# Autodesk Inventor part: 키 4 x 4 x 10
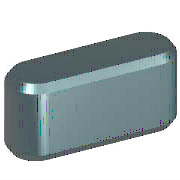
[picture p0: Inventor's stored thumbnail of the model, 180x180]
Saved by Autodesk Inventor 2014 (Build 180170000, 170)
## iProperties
IsCustomPart: 1
Created: 2012-02
Part Number: 키 4 x 4 x 10
Material: 강철, 연강
Description: 키 및 해당 키홈
Document SubType Name: Modeling
Standard: KS B 1311
Designer: test
Standards Organization: KS
Language: ko-KR
Size Designation: 4 x 4 x 10
Categories: <MemberInstance><Categories><Category DisplayName="샤프트 부품" InternalName="7f7aeb1f-a693-4053-b835-cee3144e0d98" Mnemonic="SHFT"><Category DisplayName="키" Interna
Density: 7.86 g/cm^3
Appearance: 강철
Mass: 1.13784 g
Surface Area: 1.6404 cm^2
Volume: 0.144763 cm^3
Author: test
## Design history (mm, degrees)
workplane "Work Plane1"
workplane "Work Plane2"
sketch "스케치1"
  geometry: L1 (2, 2)-(8, 2); L2 (8, -2)-(2, -2); L3 (0, 9.4)-(0, -7.4) reference; L4 (-5, 0)-(30, 0) reference; L5 (10, 0)-(10, 7); A1 r 2 centre (2, 0) between (2, 2) and (2, -2); A2 r 2 centre (8, 0) between (8, -2) and (8, 2)
  constraints: 6 end point, 5 point on circle, 4 tangent, 3 point on line, 2 centre point, 1 horizontal, 1 parallel, 1 perpendicular
  dimensions: "d0" = 2 radius of A1 (= 0.5 x PB); "d13" = 2 radius of A2 (= 0.5 x PB); "d14" = 10 distance between parallel lines of L5 L3 (= NLG)
extrude "본체1" new body sketch "스케치1" taper "d3" = 0 deg; stored distance "d4" = 10
workplane "Work Plane3"
body "Solid1"
chamfer "모따기1" distance "d8" = 0.25 (= PHH); stored, may be unused: second distance "d9" = 0.25 (= PHH), angle "d15" = 45 deg
other parameters: "d1" = -2.5 (= -PNT), "d2" = 1.5 (= PH - PNT), "NLG" = 10 [user parameter; used in 3 equation terms], "PB" = 4 [user parameter; used in 2 equation terms], "PNT" = 2.5 [user parameter; used in 2 equation terms], "PH" = 4 [user parameter; used in 1 equation term], "PHH" = 0.25 [user parameter; used in 2 equation terms], "d10" = 0, "d16" = 0, "d17" = 0, "d18" = 0, "WDMAX" = 12 [user parameter], "RR" = 0.08 [user parameter], "PUEB" = 1.8 [user parameter]
